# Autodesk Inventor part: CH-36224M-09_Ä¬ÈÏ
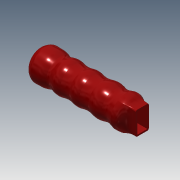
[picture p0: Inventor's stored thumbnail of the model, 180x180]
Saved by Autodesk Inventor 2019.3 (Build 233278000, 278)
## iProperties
Created: 2010-06
Part Number: CH-36224M-09_Ä¬ÈÏ
Material: Ogólny
Document SubType Name: Modeling
Designer: CADENGINEERING4
Density: 1 g/cm^3
Appearance: Czerwona
Author: CADENGINEERING4
Revision Number: ÈÎºÎ
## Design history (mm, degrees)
feature "NONE"
node "Bryła1"
